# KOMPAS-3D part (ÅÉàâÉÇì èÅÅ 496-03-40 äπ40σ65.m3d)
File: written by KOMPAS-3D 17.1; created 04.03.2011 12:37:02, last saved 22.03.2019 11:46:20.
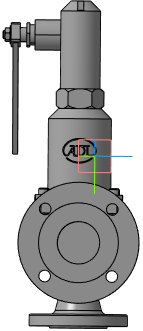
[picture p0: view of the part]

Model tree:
1. Плоскость XY
2. Плоскость ZX
3. Плоскость ZY
4. Ось X
5. Ось Y
6. Ось Z
7. Начало координат
8. Операция без истории:2

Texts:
  Viktor2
